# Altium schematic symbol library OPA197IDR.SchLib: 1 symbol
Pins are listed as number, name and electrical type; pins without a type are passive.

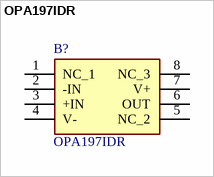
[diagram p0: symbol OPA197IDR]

## OPA197IDR
designator B?
36-V, Precision, Rail-to-Rail Input Output, Low Offset Voltage Op Amp; Manufacturer_Name: Texas Instruments; Geometry.Height: 1.75mm
footprint SOIC127P600X175-8N
pins: 1 NC_1, 2 -IN, 3 +IN, 4 V-, 5 NC_2, 6 OUT, 7 V+, 8 NC_3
